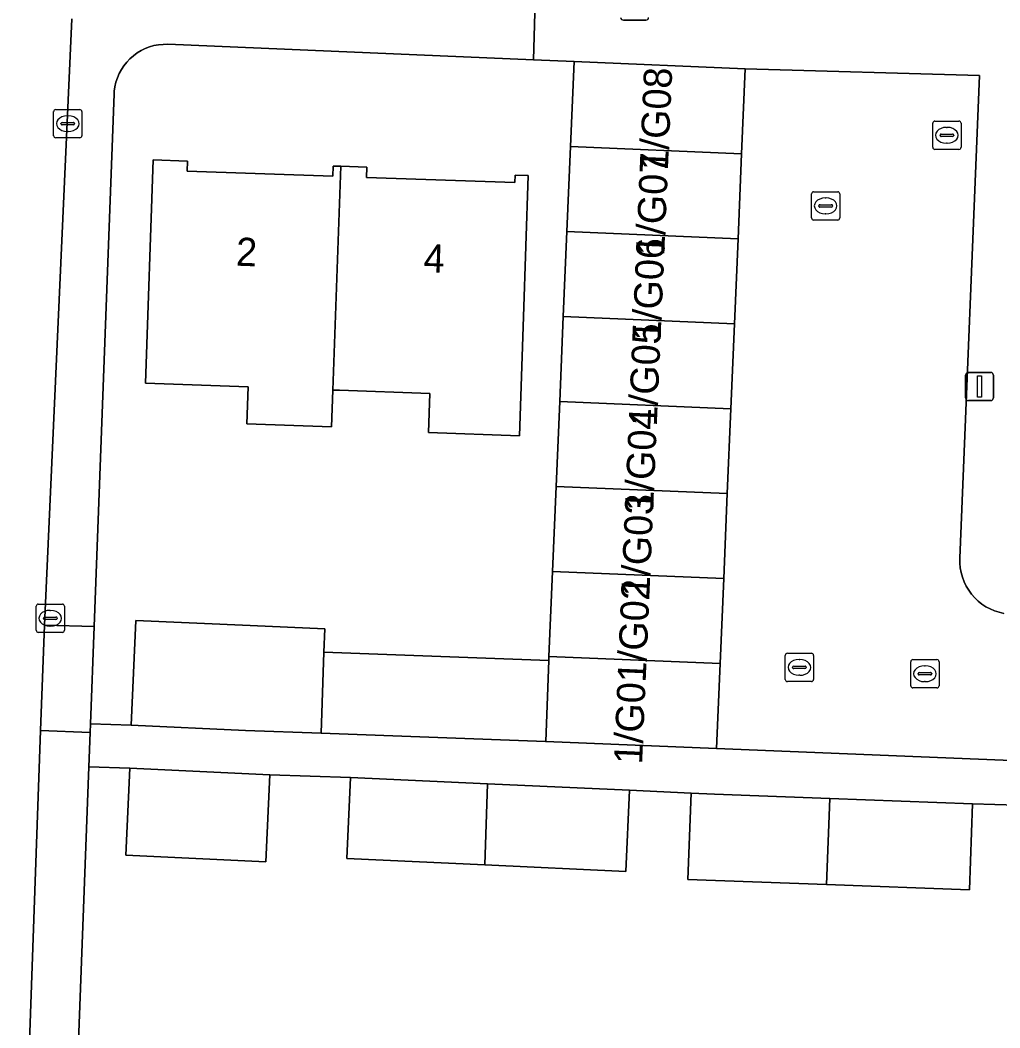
# Model space of a CAD drawing. Extents: x 161354 to 162026, y 386504 to 387460.
# Drawn here: x 161506.15 to 161540.83, y 387313.91 to 387349.57 of the extents above; entities that cross this region are included whole.
import ezdxf

# ---------------------------------------------------------------- set-up
doc = ezdxf.new("R2010")
doc.units = 0
for name, color, linetype in [('IMGEO_Erf', 7, 'Continuous'), ('IMGEO_Kolk', 7, 'Continuous'), ('IMGEO_Lichtmast', 7, 'Continuous'), ('IMGEO_Pand', 7, 'Continuous'), ('IMGEO_Pand_nummerreeks', 7, 'Continuous'), ('IMGEO_Rijbaan_lokaal_open', 7, 'Continuous'), ('IMGEO_Rioolput', 7, 'Continuous'), ('IMGEO_Voetpad_open', 7, 'Continuous')]:
    doc.layers.add(name, color=color, linetype=linetype)

msp = doc.modelspace()

# ---------------------------------------------------------------- linework, layer by layer
at = {"layer": 'IMGEO_Erf'}
for points in [[(161525.122, 387333.072), (161525.249, 387336.08), (161525.376, 387339.087), (161525.503, 387342.094), (161525.63, 387345.101), (161525.757, 387348.108), (161524.316, 387348.169), (161511.375, 387348.717), (161511.212, 387348.716), (161511.049, 387348.7), (161510.889, 387348.67), (161510.731, 387348.626), (161510.579, 387348.568), (161510.432, 387348.496), (161510.292, 387348.412), (161510.161, 387348.315), (161510.038, 387348.207), (161509.926, 387348.089), (161509.824, 387347.961), (161509.735, 387347.824), (161509.658, 387347.68), (161509.594, 387347.53), (161509.544, 387347.375), (161509.508, 387347.215), (161509.486, 387347.054), (161509.48, 387346.96), (161508.77, 387328.112), (161508.64, 387324.668), (161510.084, 387324.621), (161510.249, 387328.33), (161514.29, 387328.151), (161516.934, 387328.034), (161516.905, 387327.211), (161524.862, 387326.917), (161524.868, 387327.058), (161524.995, 387330.065)], [(161517.45, 387336.476), (161517.222, 387336.484), (161517.176, 387335.18), (161514.176, 387335.283), (161514.222, 387336.603), (161510.593, 387336.728), (161510.864, 387344.627), (161512.074, 387344.586), (161512.062, 387344.228), (161517.22, 387344.051), (161517.232, 387344.409), (161517.504, 387344.4), (161518.427, 387344.368), (161518.415, 387344.002), (161523.658, 387343.822), (161523.668, 387344.092), (161524.138, 387344.076), (161523.967, 387339.079), (161523.822, 387334.868), (161520.607, 387334.979), (161520.655, 387336.366)]]:
    msp.add_lwpolyline(points, close=True, dxfattribs=at)
msp.add_lwpolyline([(161542.226, 387321.771), (161539.863, 387321.843), (161539.749, 387318.795), (161534.688, 387318.985), (161529.786, 387319.169), (161529.901, 387322.217), (161527.72, 387322.323), (161527.588, 387319.446), (161522.604, 387319.681), (161517.719, 387319.912), (161517.85, 387322.773), (161514.987, 387322.873), (161514.845, 387319.794), (161509.889, 387320.023), (161510.031, 387323.102), (161508.583, 387323.155), (161507.816, 387302.794)], dxfattribs=at)
at = {"layer": 'IMGEO_Kolk'}
for p, q in [((161507.414, 387346.409), (161508.266, 387346.409)), ((161507.339, 387345.483), (161507.339, 387346.335)), ((161507.827, 387346.189), (161507.852, 387346.189)), ((161508.34, 387346.335), (161508.34, 387345.483)), ((161538.525, 387345.999), (161539.377, 387345.999)), ((161507.598, 387345.903), (161507.598, 387345.915)), ((161508.036, 387345.866), (161507.638, 387345.866)), ((161507.641, 387345.952), (161508.039, 387345.952)), ((161507.85, 387345.629), (161507.825, 387345.629)), ((161508.082, 387345.915), (161508.082, 387345.903)), ((161538.45, 387345.073), (161538.45, 387345.925)), ((161538.938, 387345.779), (161538.963, 387345.779)), ((161539.451, 387345.925), (161539.451, 387345.073)), ((161508.266, 387345.409), (161507.414, 387345.409)), ((161538.709, 387345.493), (161538.709, 387345.505)), ((161539.147, 387345.456), (161538.749, 387345.456)), ((161538.752, 387345.542), (161539.15, 387345.542)), ((161539.193, 387345.505), (161539.193, 387345.493)), ((161539.377, 387344.999), (161538.525, 387344.999)), ((161538.961, 387345.219), (161538.936, 387345.219)), ((161506.794, 387328.907), (161507.646, 387328.907)), ((161506.719, 387327.981), (161506.719, 387328.833)), ((161507.207, 387328.687), (161507.232, 387328.687)), ((161507.72, 387328.833), (161507.72, 387327.981)), ((161506.978, 387328.401), (161506.978, 387328.413)), ((161507.416, 387328.364), (161507.018, 387328.364)), ((161507.021, 387328.45), (161507.419, 387328.45)), ((161507.462, 387328.413), (161507.462, 387328.401)), ((161507.646, 387327.907), (161506.794, 387327.907)), ((161507.23, 387328.127), (161507.205, 387328.127)), ((161537.673, 387326.019), (161537.673, 387326.871)), ((161537.748, 387326.945), (161538.6, 387326.945)), ((161538.674, 387326.871), (161538.674, 387326.019)), ((161537.932, 387326.439), (161537.932, 387326.451)), ((161538.37, 387326.402), (161537.972, 387326.402)), ((161537.975, 387326.488), (161538.373, 387326.488)), ((161538.161, 387326.725), (161538.186, 387326.725)), ((161538.416, 387326.451), (161538.416, 387326.439)), ((161538.184, 387326.165), (161538.159, 387326.165)), ((161538.6, 387325.945), (161537.748, 387325.945))]:
    msp.add_line(p, q, dxfattribs=at)
for points in [[(161507.414, 387346.409), (161508.266, 387346.409)], [(161507.339, 387345.483), (161507.339, 387346.335)], [(161508.34, 387346.335), (161508.34, 387345.483)], [(161538.525, 387345.999), (161539.377, 387345.999)], [(161538.45, 387345.073), (161538.45, 387345.925)], [(161539.451, 387345.925), (161539.451, 387345.073)], [(161508.266, 387345.409), (161507.414, 387345.409)], [(161539.377, 387344.999), (161538.525, 387344.999)], [(161506.794, 387328.907), (161507.646, 387328.907)], [(161506.719, 387327.981), (161506.719, 387328.833)], [(161507.72, 387328.833), (161507.72, 387327.981)], [(161507.646, 387327.907), (161506.794, 387327.907)], [(161537.673, 387326.019), (161537.673, 387326.871)], [(161537.748, 387326.945), (161538.6, 387326.945)], [(161538.674, 387326.871), (161538.674, 387326.019)], [(161538.6, 387325.945), (161537.748, 387325.945)]]:
    msp.add_lwpolyline(points, dxfattribs=at)
for centre, radius, start, end in [((161507.416, 387346.333), 0.0765, 91.552, 178.448), ((161507.416, 387346.333), 0.0765, 91.552, 178.448), ((161508.264, 387346.333), 0.0765, 1.552, 88.448), ((161508.264, 387346.333), 0.0765, 1.552, 88.448), ((161538.527, 387345.923), 0.0765, 91.552, 178.448), ((161538.527, 387345.923), 0.0765, 91.552, 178.448), ((161539.375, 387345.923), 0.0765, 1.552, 88.448), ((161539.375, 387345.923), 0.0765, 1.552, 88.448), ((161507.638, 387345.912), 0.0403, 85.8775, 175.7526), ((161507.635, 387345.902), 0.0366, 178.938, 274.7102), ((161508.039, 387345.909), 0.043, 264.8664, 352.4533), ((161508.043, 387345.914), 0.0386, 1.7309, 96.639), ((161507.416, 387345.485), 0.0765, 181.552, 268.448), ((161507.416, 387345.485), 0.0765, 181.552, 268.448), ((161508.264, 387345.485), 0.0765, 271.552, 358.448), ((161508.264, 387345.485), 0.0765, 271.552, 358.448), ((161538.749, 387345.502), 0.0403, 85.8775, 175.7526), ((161538.746, 387345.492), 0.0366, 178.938, 274.7102), ((161539.15, 387345.499), 0.043, 264.8664, 352.4533), ((161539.154, 387345.504), 0.0386, 1.7309, 96.639), ((161538.527, 387345.075), 0.0765, 181.552, 268.448), ((161538.527, 387345.075), 0.0765, 181.552, 268.448), ((161539.375, 387345.075), 0.0765, 271.552, 358.448), ((161539.375, 387345.075), 0.0765, 271.552, 358.448), ((161506.796, 387328.831), 0.0765, 91.552, 178.448), ((161506.796, 387328.831), 0.0765, 91.552, 178.448), ((161507.644, 387328.831), 0.0765, 1.552, 88.448), ((161507.644, 387328.831), 0.0765, 1.552, 88.448), ((161507.018, 387328.41), 0.0403, 85.8775, 175.7526), ((161507.015, 387328.4), 0.0366, 178.938, 274.7102), ((161507.419, 387328.407), 0.043, 264.8664, 352.4533), ((161507.423, 387328.412), 0.0386, 1.7309, 96.639), ((161506.796, 387327.983), 0.0765, 181.552, 268.448), ((161506.796, 387327.983), 0.0765, 181.552, 268.448), ((161507.644, 387327.983), 0.0765, 271.552, 358.448), ((161507.644, 387327.983), 0.0765, 271.552, 358.448), ((161537.75, 387326.869), 0.0765, 91.552, 178.448), ((161537.75, 387326.869), 0.0765, 91.552, 178.448), ((161538.598, 387326.869), 0.0765, 1.552, 88.448), ((161538.598, 387326.869), 0.0765, 1.552, 88.448), ((161537.972, 387326.448), 0.0403, 85.8775, 175.7526), ((161537.969, 387326.438), 0.0366, 178.938, 274.7102), ((161538.373, 387326.445), 0.043, 264.8664, 352.4533), ((161538.377, 387326.45), 0.0386, 1.7309, 96.639), ((161537.75, 387326.021), 0.0765, 181.552, 268.448), ((161537.75, 387326.021), 0.0765, 181.552, 268.448), ((161538.598, 387326.021), 0.0765, 271.552, 358.448), ((161538.598, 387326.021), 0.0765, 271.552, 358.448)]:
    msp.add_arc(centre, radius, start, end, dxfattribs=at)
for centre, major_axis, ratio, start_param, end_param in [((161507.826, 387345.909), (-0.387, 0.002), 0.722429, 4.712389, 7.853982), ((161507.851, 387345.909), (-0.39, 0.002), 0.717154, 1.570796, 4.712389), ((161538.937, 387345.499), (-0.387, 0.002), 0.722429, 4.712389, 7.853982), ((161538.962, 387345.499), (-0.39, 0.002), 0.717154, 1.570796, 4.712389), ((161507.206, 387328.407), (-0.387, 0.002), 0.722429, 4.712389, 7.853982), ((161507.231, 387328.407), (-0.39, 0.002), 0.717154, 1.570796, 4.712389), ((161538.16, 387326.445), (-0.387, 0.002), 0.722429, 4.712389, 7.853982), ((161538.185, 387326.445), (-0.39, 0.002), 0.717154, 1.570796, 4.712389)]:
    msp.add_ellipse(centre, major_axis=major_axis, ratio=ratio, start_param=start_param, end_param=end_param, dxfattribs=at)
at = {"layer": 'IMGEO_Lichtmast'}
for p, q in [((161528.296, 387349.572), (161527.506, 387349.572)), ((161527.506, 387349.572), (161528.296, 387349.572)), ((161539.711, 387337.11), (161540.501, 387337.11)), ((161540.501, 387337.11), (161539.711, 387337.11)), ((161539.611, 387336.21), (161539.611, 387337.01)), ((161539.611, 387337.01), (161539.611, 387336.21)), ((161540.601, 387337.01), (161540.601, 387336.21)), ((161540.601, 387336.21), (161540.601, 387337.01)), ((161540.501, 387336.11), (161539.711, 387336.11)), ((161539.711, 387336.11), (161540.501, 387336.11))]:
    msp.add_line(p, q, dxfattribs=at)
msp.add_lwpolyline([(161540.031, 387336.985), (161540.181, 387336.985), (161540.181, 387336.235), (161540.031, 387336.235), (161540.031, 387336.985)], dxfattribs=at)
for centre, start, end in [((161527.506, 387349.672), 180, 270), ((161527.506, 387349.672), 180, 270), ((161528.296, 387349.672), 270, 0), ((161528.296, 387349.672), 270, 0), ((161539.711, 387337.01), 90, 180), ((161539.711, 387337.01), 90, 180), ((161540.501, 387337.01), 0, 90), ((161540.501, 387337.01), 360, 90), ((161539.711, 387336.21), 180, 270), ((161539.711, 387336.21), 180, 270), ((161540.501, 387336.21), 270, 0), ((161540.501, 387336.21), 270, 0)]:
    msp.add_arc(centre, 0.1, start, end, dxfattribs=at)
at = {"layer": 'IMGEO_Pand'}
for points in [[(161525.757, 387348.108), (161525.63, 387345.101), (161531.686, 387344.846), (161531.813, 387347.853)], [(161531.686, 387344.846), (161525.63, 387345.101), (161525.503, 387342.094), (161531.559, 387341.838)], [(161517.504, 387344.4), (161517.232, 387344.409), (161517.22, 387344.051), (161512.062, 387344.228), (161512.074, 387344.586), (161510.864, 387344.627), (161510.593, 387336.728), (161514.222, 387336.603), (161514.176, 387335.283), (161517.176, 387335.18), (161517.222, 387336.484)], [(161524.138, 387344.076), (161523.668, 387344.092), (161523.658, 387343.822), (161518.415, 387344.002), (161518.427, 387344.368), (161517.504, 387344.4), (161517.222, 387336.484), (161517.45, 387336.476), (161520.655, 387336.366), (161520.607, 387334.979), (161523.822, 387334.868), (161523.967, 387339.079)], [(161531.559, 387341.838), (161525.503, 387342.094), (161525.376, 387339.087), (161531.432, 387338.831)], [(161531.432, 387338.831), (161525.376, 387339.087), (161525.249, 387336.08), (161531.306, 387335.824)], [(161531.306, 387335.824), (161525.249, 387336.08), (161525.122, 387333.072), (161531.179, 387332.817)], [(161531.179, 387332.817), (161525.122, 387333.072), (161524.995, 387330.065), (161531.052, 387329.81)], [(161531.052, 387329.81), (161524.995, 387330.065), (161524.868, 387327.058), (161530.925, 387326.802)], [(161516.905, 387327.211), (161516.934, 387328.034), (161514.29, 387328.151), (161510.249, 387328.33), (161510.084, 387324.621), (161514.125, 387324.442), (161516.805, 387324.343)], [(161524.741, 387324.05), (161524.756, 387324.049), (161524.862, 387326.917), (161516.905, 387327.211), (161516.805, 387324.343)], [(161530.798, 387323.795), (161530.925, 387326.802), (161524.868, 387327.058), (161524.862, 387326.917), (161524.756, 387324.049)], [(161514.987, 387322.873), (161510.031, 387323.102), (161509.889, 387320.023), (161514.845, 387319.794)], [(161522.693, 387322.552), (161517.85, 387322.773), (161517.719, 387319.912), (161522.604, 387319.681)], [(161522.604, 387319.681), (161527.588, 387319.446), (161527.72, 387322.323), (161522.693, 387322.552)], [(161534.803, 387322.033), (161530.732, 387322.186), (161529.901, 387322.217), (161529.786, 387319.169), (161534.688, 387318.985)], [(161534.688, 387318.985), (161539.749, 387318.795), (161539.863, 387321.843), (161534.803, 387322.033)]]:
    msp.add_lwpolyline(points, close=True, dxfattribs=at)
at = {"layer": 'IMGEO_Rijbaan_lokaal_open'}
for points in [[(161506.153, 387302.221), (161506.407, 387311.079), (161506.872, 387324.432), (161507.019, 387328.161), (161507.982, 387349.624)], [(161540.971, 387328.58), (161540.805, 387328.618), (161540.642, 387328.67), (161540.486, 387328.737), (161540.335, 387328.818), (161540.193, 387328.912), (161540.059, 387329.018), (161539.936, 387329.135), (161539.823, 387329.263), (161539.723, 387329.401), (161539.635, 387329.547), (161539.561, 387329.701), (161539.5, 387329.86), (161539.454, 387330.024), (161539.423, 387330.192), (161539.407, 387330.361), (161539.406, 387330.532), (161540.1, 387347.609), (161531.813, 387347.853), (161531.686, 387344.846), (161531.559, 387341.838), (161531.432, 387338.831), (161531.306, 387335.824), (161531.179, 387332.817), (161531.052, 387329.81), (161530.925, 387326.802), (161530.798, 387323.795), (161561.221, 387322.559)]]:
    msp.add_lwpolyline(points, dxfattribs=at)
at = {"layer": 'IMGEO_Rioolput'}
for p, q in [((161534.235, 387343.5), (161535.087, 387343.5)), ((161534.16, 387342.574), (161534.16, 387343.426)), ((161534.648, 387343.28), (161534.673, 387343.28)), ((161535.161, 387343.426), (161535.161, 387342.574)), ((161534.419, 387342.994), (161534.419, 387343.006)), ((161534.857, 387342.957), (161534.459, 387342.957)), ((161534.462, 387343.043), (161534.86, 387343.043)), ((161534.903, 387343.006), (161534.903, 387342.994)), ((161535.087, 387342.5), (161534.235, 387342.5)), ((161534.671, 387342.72), (161534.646, 387342.72)), ((161533.231, 387326.244), (161533.231, 387327.096)), ((161533.306, 387327.17), (161534.158, 387327.17)), ((161534.232, 387327.096), (161534.232, 387326.244)), ((161533.719, 387326.95), (161533.744, 387326.95)), ((161533.49, 387326.664), (161533.49, 387326.676)), ((161533.928, 387326.627), (161533.53, 387326.627)), ((161533.533, 387326.713), (161533.931, 387326.713)), ((161533.742, 387326.39), (161533.717, 387326.39)), ((161533.974, 387326.676), (161533.974, 387326.664)), ((161534.158, 387326.17), (161533.306, 387326.17))]:
    msp.add_line(p, q, dxfattribs=at)
for points in [[(161534.235, 387343.5), (161535.087, 387343.5)], [(161534.16, 387342.574), (161534.16, 387343.426)], [(161535.161, 387343.426), (161535.161, 387342.574)], [(161535.087, 387342.5), (161534.235, 387342.5)], [(161533.231, 387326.244), (161533.231, 387327.096)], [(161533.306, 387327.17), (161534.158, 387327.17)], [(161534.232, 387327.096), (161534.232, 387326.244)], [(161534.158, 387326.17), (161533.306, 387326.17)]]:
    msp.add_lwpolyline(points, dxfattribs=at)
for centre, radius, start, end in [((161534.237, 387343.424), 0.0765, 91.552, 178.448), ((161534.237, 387343.424), 0.0765, 91.552, 178.448), ((161535.085, 387343.424), 0.0765, 1.552, 88.448), ((161535.085, 387343.424), 0.0765, 1.552, 88.448), ((161534.459, 387343.003), 0.0403, 85.8775, 175.7526), ((161534.456, 387342.993), 0.0366, 178.938, 274.7102), ((161534.86, 387343), 0.043, 264.8664, 352.4533), ((161534.864, 387343.005), 0.0386, 1.7309, 96.639), ((161534.237, 387342.576), 0.0765, 181.552, 268.448), ((161534.237, 387342.576), 0.0765, 181.552, 268.448), ((161535.085, 387342.576), 0.0765, 271.552, 358.448), ((161535.085, 387342.576), 0.0765, 271.552, 358.448), ((161533.308, 387327.094), 0.0765, 91.552, 178.448), ((161533.308, 387327.094), 0.0765, 91.552, 178.448), ((161534.156, 387327.094), 0.0765, 1.552, 88.448), ((161534.156, 387327.094), 0.0765, 1.552, 88.448), ((161533.53, 387326.673), 0.0403, 85.8775, 175.7526), ((161533.527, 387326.663), 0.0366, 178.938, 274.7102), ((161533.931, 387326.67), 0.043, 264.8664, 352.4533), ((161533.935, 387326.675), 0.0386, 1.7309, 96.639), ((161533.308, 387326.246), 0.0765, 181.552, 268.448), ((161533.308, 387326.246), 0.0765, 181.552, 268.448), ((161534.156, 387326.246), 0.0765, 271.552, 358.448), ((161534.156, 387326.246), 0.0765, 271.552, 358.448)]:
    msp.add_arc(centre, radius, start, end, dxfattribs=at)
for centre, major_axis, ratio, start_param, end_param in [((161534.647, 387343), (-0.387, 0.002), 0.722429, 4.712389, 7.853982), ((161534.672, 387343), (-0.39, 0.002), 0.717154, 1.570796, 4.712389), ((161533.718, 387326.67), (-0.387, 0.002), 0.722429, 4.712389, 7.853982), ((161533.743, 387326.67), (-0.39, 0.002), 0.717154, 1.570796, 4.712389)]:
    msp.add_ellipse(centre, major_axis=major_axis, ratio=ratio, start_param=start_param, end_param=end_param, dxfattribs=at)
at = {"layer": 'IMGEO_Voetpad_open'}
for points in [[(161507.982, 387349.624), (161507.019, 387328.161), (161508.77, 387328.112), (161509.48, 387346.96), (161509.486, 387347.054), (161509.508, 387347.215), (161509.544, 387347.375), (161509.594, 387347.53), (161509.658, 387347.68), (161509.735, 387347.824), (161509.824, 387347.961), (161509.926, 387348.089), (161510.038, 387348.207), (161510.161, 387348.315), (161510.292, 387348.412), (161510.432, 387348.496), (161510.579, 387348.568), (161510.731, 387348.626), (161510.889, 387348.67), (161511.049, 387348.7), (161511.212, 387348.716), (161511.375, 387348.717), (161524.316, 387348.169), (161524.391, 387350.667)], [(161524.391, 387350.667), (161524.316, 387348.169), (161525.757, 387348.108), (161531.813, 387347.853), (161540.1, 387347.609), (161539.406, 387330.532), (161539.407, 387330.361), (161539.423, 387330.192), (161539.454, 387330.024), (161539.5, 387329.86), (161539.561, 387329.701), (161539.635, 387329.547), (161539.723, 387329.401), (161539.823, 387329.263), (161539.936, 387329.135), (161540.059, 387329.018), (161540.193, 387328.912), (161540.335, 387328.818), (161540.486, 387328.737), (161540.642, 387328.67), (161540.805, 387328.618), (161540.971, 387328.58)], [(161561.221, 387322.559), (161530.798, 387323.795), (161524.756, 387324.049), (161524.741, 387324.05), (161516.805, 387324.343), (161514.125, 387324.442), (161510.084, 387324.621), (161508.64, 387324.668), (161508.629, 387324.365), (161508.583, 387323.155), (161510.031, 387323.102), (161514.987, 387322.873), (161517.85, 387322.773), (161522.693, 387322.552), (161527.72, 387322.323), (161529.901, 387322.217), (161530.732, 387322.186), (161534.803, 387322.033), (161539.863, 387321.843), (161542.226, 387321.771)], [(161508.583, 387323.155), (161508.629, 387324.365), (161506.872, 387324.432), (161506.407, 387311.079), (161506.153, 387302.221)], [(161507.816, 387302.794), (161508.583, 387323.155)]]:
    msp.add_lwpolyline(points, dxfattribs=at)
msp.add_lwpolyline([(161508.77, 387328.112), (161507.019, 387328.161), (161506.872, 387324.432), (161508.629, 387324.365), (161508.64, 387324.668)], close=True, dxfattribs=at)

# ---------------------------------------------------------------- texts
at = {"layer": 'IMGEO_Pand_nummerreeks'}
for s, rotation, p in [('1/G08', 87.5104, (161529.076, 387344.239)), ('1/G07', 87.5104, (161528.945, 387341.219)), ('2', 358.0004, (161513.779, 387340.885)), ('1/G06', 87.5104, (161528.814, 387338.202)), ('4', 358.0004, (161520.419, 387340.654)), ('1/G05', 87.5104, (161528.683, 387335.185)), ('1/G04', 87.5104, (161528.552, 387332.168)), ('1/G03', 87.5104, (161528.42, 387329.151)), ('1/G02', 87.5104, (161528.289, 387326.127)), ('1/G01', 87.5104, (161528.163, 387323.227))]:
    msp.add_text(s, height=1, rotation=rotation, dxfattribs=at).set_placement(p)

doc.saveas('drawing.dxf')
